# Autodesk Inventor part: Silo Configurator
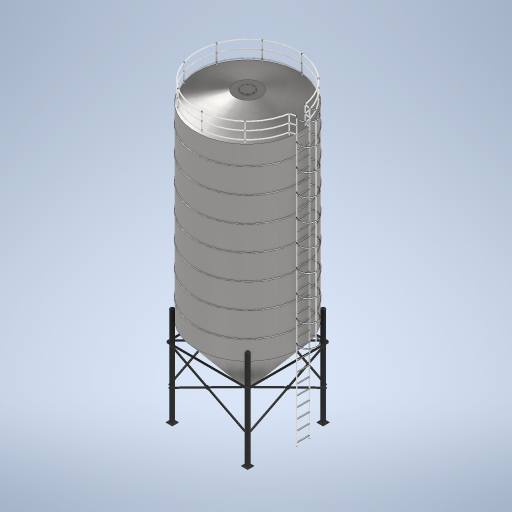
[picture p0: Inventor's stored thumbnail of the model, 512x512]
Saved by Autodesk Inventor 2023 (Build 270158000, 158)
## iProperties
Company: BIG Silos
Created: 2022-04
Part Number: Silo Configurator
Material: Generic
Document SubType Name: Modeling
Designer: Admin
Density: 1 g/cm^3
Appearance: Semi-Polished
Author: Cadflair
Title: Silo Quote 1234
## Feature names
1. Silo Revolution [Revolution]
2. Cap Extrusion [Extrusion]
3. Nut Extrusion [Extrusion]
4. Nut Pattern [Circular Pattern]
5. Rib Revolution [Revolution]
6. Rib Pattern [Rectangular Pattern]
7. Footpad Extrusion [Extrusion]
8. Leg Extrusion [Extrusion]
9. Footpad Rib Pattern [Circular Pattern]
10. Leg Pattern [Circular Pattern]
11. Fillet1
12. Brace Extrusion [Extrusion]
13. Brace Pattern [Rectangular Pattern]
14. Brace Circular [Circular Pattern]
15. Ladder Extrusion [Extrusion]
16. Ladder Backbone Extrusion [Extrusion]
17. Ladder Cage Extrusion [Extrusion]
18. Rung Extrusion [Extrusion]
19. Rung Pattern [Rectangular Pattern]
20. Cage Pattern [Rectangular Pattern]
21. Post Extrusion [Extrusion]
22. Post Pattern [Circular Pattern]
23. Railing Sweep
24. Rectangular Pattern5
## Parameters: outletDiam = 355.6 mm, wallThickness = 25.4 mm, innerDiam = 4876.8 mm, outletStubHeight = 50.8 mm, siloHeight = 12192 mm, d7 = 90 deg, ribDiam = 50.8 mm, verticalSideWallHeight = 8950.29044 mm, d18 = 90 deg, ribPatternDistance = 7121.49044 mm, platformDiam = 1219.2 mm, topslope = 15 deg, coneAngle = 50 deg, dischargeHeight = 1524 mm, d31 = 4876.8 mm, footPadWidth = 304.8 mm, footPadLength = 304.8 mm, legTubeDiam = 203.2 mm, d35 = 12.7 mm, d36 = 0, legMountingOffset = 457.2 mm, d38 = 12.7 mm, d39 = 0, footpadRibOffset = 12.7 mm, footpadRibAngle = 60 deg, d42 = 2.54 mm, footpadRibThickness = 12.7 mm, d44 = 0, d45 = 0, d46 = 2.54 mm, d47 = 2.54 mm, d49 = 360 deg, d52 = 360 deg, horizontalBraceWidth = 50.8 mm, angleBraceWidth = 50.8 mm, horizontalBraceSpacing = 1828.8 mm, d57 = 50.8 mm, d58 = 0, d59 = 152.4 mm, d62 = 1828.8 mm, d64 = 360 deg, ladderWidth = 609.6 mm, ladderDiam = 50.8 mm, ladderAngle = 90 deg, ladderRadius = 2641.6 mm, ladderOffsetHeight = 508 mm, d75 = 38.1 mm, rungOffsetHeight = 152.4 mm, rungThickness = 25.4 mm, d78 = 0, rungDistance = 12558.76861 mm, d83 = 50.8 mm, d88 = 152.4 mm, d89 = 0, ladderHeight = 13625.56861 mm, ladderOvershoot = 914.4 mm, rungSpacing = 457.2 mm, d93 = 609.6 mm, d94 = 6.35 mm, ladderCageStrapWidth = 50.8 mm, d96 = 0, d97 = 76.2 mm, d98 = 0, ladderCageHeight = 9407.49044 mm, cageDistance = 9356.69044 mm, cageSpacing = 914.4 mm, postDiam = 50.8 mm, ladderOpeningAngle = 3.20519 mm, d106 = 50.8 mm, d107 = 0, d109 = 59.62666 mm, d113 = 50.8 mm, d114 = 0, d115 = 0, ladderRadialOffset = 203.2 mm, railingPatternDistance = 762 mm, bracingOffsetHeight = 203.2 mm, bracingSpan = 3123.404 mm, capDiam = 609.6 mm, d123 = 25.4 mm, d124 = 25.4 mm, d125 = 12.7 mm, d126 = 25.4 mm, d127 = 0, d128 = 12.7 mm, d129 = 0, d131 = 360 deg, ribOffset = 914.4 mm, d136 = 762 mm, d137 = 76.2 mm
